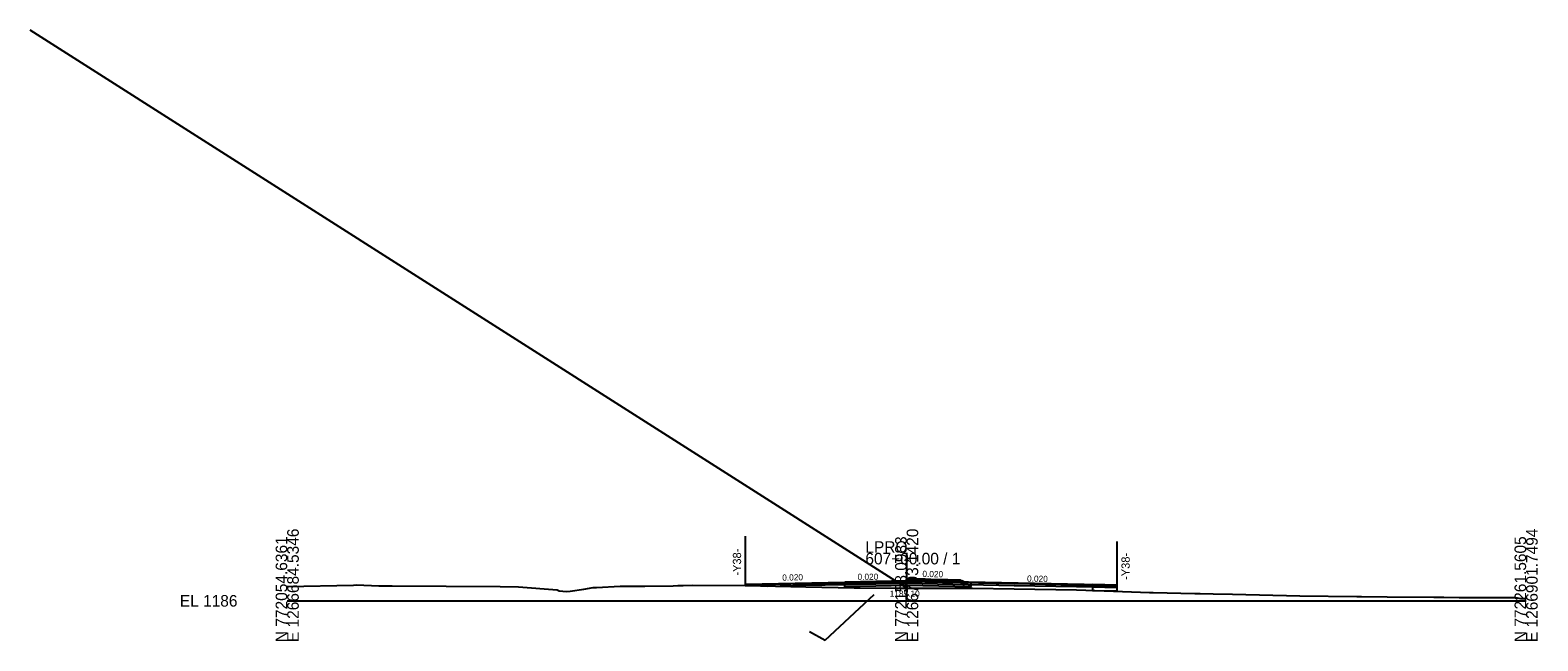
# Model space of a CAD drawing. Extents: x -3833 to 1267678, y -522 to 773248.
# Drawn here: x 937.8 to 1302.8, y 7990.3 to 8138.2 of the extents above; entities that cross this region are included whole.
import ezdxf

# ---------------------------------------------------------------- set-up
doc = ezdxf.new("R2010")
doc.units = 0
for name, color, linetype in [('Exist Cross Section Cell', 7, 'Continuous'), ('Exist XS Center Line Elevation Label', 7, 'Continuous'), ('Exist XS Ground Line', 7, 'Continuous'), ('Prop CMT DNC', 7, 'Continuous'), ('Prop CMT Pvmt Course 1', 7, 'Continuous'), ('Prop CMT Pvmt Course 2', 7, 'Continuous'), ('Prop CMT Pvmt Course 3', 7, 'Continuous'), ('Prop CMT Pvmt Course 4', 7, 'Continuous'), ('Prop CMT Shld Paved Course 1', 7, 'Continuous'), ('Prop CMT Shld Paved Course 2', 7, 'Continuous'), ('Prop CMT Subgrade Earthwork', 7, 'Continuous'), ('Prop Conc Curb and Gutter', 7, 'Continuous'), ('Prop Conc Island Cover', 7, 'Continuous'), ('Prop Corridor Mesh Bottom', 7, 'Continuous'), ('Prop XS Finish Grade', 7, 'Continuous'), ('Prop XS SE Text', 7, 'Continuous'), ('Prop XS Shear Point Element', 7, 'Continuous'), ('Prop XS Shear Point Label', 7, 'Continuous'), ('Scratch_Level_1', 7, 'Continuous'), ('Scratch_Level_5', 7, 'Continuous')]:
    doc.layers.add(name, color=color, linetype=linetype)

msp = doc.modelspace()

# ---------------------------------------------------------------- linework, layer by layer
at = {"layer": 'Exist Cross Section Cell'}
for p, q in [((1150, 8000), (1150, 8011.62)), ((1000, 8000), (1150, 8000)), ((1150, 8000), (1300, 8000))]:
    msp.add_line(p, q, dxfattribs=at)
at = {"layer": 'Exist XS Ground Line'}
for p, q in [((1000, 8003.45), (1016.03, 8003.78)), ((1016.03, 8003.78), (1016.76, 8003.87)), ((1016.76, 8003.87), (1022.17, 8003.64)), ((1022.17, 8003.64), (1025.41, 8003.65)), ((1025.41, 8003.65), (1051.56, 8003.47)), ((1051.56, 8003.47), (1056.01, 8003.4)), ((1056.01, 8003.4), (1065.39, 8002.68)), ((1068.55, 8002.3), (1071.81, 8002.83)), ((1071.81, 8002.83), (1074.05, 8003.22)), ((1074.05, 8003.22), (1074.91, 8003.25)), ((1074.91, 8003.25), (1080.65, 8003.54)), ((1080.65, 8003.54), (1082.76, 8003.54)), ((1082.76, 8003.54), (1086.56, 8003.58)), ((1086.56, 8003.58), (1093.44, 8003.65)), ((1093.44, 8003.65), (1094.58, 8003.67)), ((1094.58, 8003.67), (1095.84, 8003.71)), ((1095.84, 8003.71), (1098.22, 8003.77)), ((1098.22, 8003.77), (1110.86, 8003.7)), ((1110.86, 8003.7), (1125.56, 8003.38)), ((1125.56, 8003.38), (1137.29, 8003.12)), ((1137.29, 8003.12), (1147.49, 8003.1)), ((1147.49, 8003.1), (1150, 8003.1)), ((1150, 8003.1), (1165.98, 8003.05)), ((1165.98, 8003.05), (1176.07, 8002.89)), ((1176.07, 8002.89), (1191.16, 8002.63)), ((1065.39, 8002.68), (1065.88, 8002.44)), ((1065.88, 8002.44), (1067.66, 8002.27)), ((1067.66, 8002.27), (1068.55, 8002.3)), ((1191.16, 8002.63), (1200.06, 8002.33)), ((1200.06, 8002.33), (1208.78, 8002)), ((1208.78, 8002), (1209.71, 8001.98)), ((1209.71, 8001.98), (1219.77, 8001.75)), ((1219.77, 8001.75), (1221.09, 8001.73)), ((1221.09, 8001.73), (1224.2, 8001.68)), ((1224.2, 8001.68), (1228.87, 8001.6)), ((1228.87, 8001.6), (1245.23, 8001.23)), ((1245.23, 8001.23), (1259.04, 8001.04)), ((1259.04, 8001.04), (1260.15, 8001.02)), ((1260.15, 8001.02), (1266.32, 8000.94)), ((1266.32, 8000.94), (1277.65, 8000.89)), ((1277.65, 8000.89), (1280.1, 8000.87)), ((1280.1, 8000.87), (1283.82, 8000.84)), ((1283.82, 8000.84), (1284.64, 8000.83)), ((1284.64, 8000.83), (1295.8, 8000.76)), ((1295.8, 8000.76), (1297.44, 8000.81)), ((1297.44, 8000.81), (1298.66, 8000.58)), ((1298.66, 8000.58), (1300, 8000.55))]:
    msp.add_line(p, q, dxfattribs=at)
at = {"layer": 'Prop CMT Pvmt Course 1'}
for p, q in [((1111, 8004.06), (1135, 8004.54)), ((1111, 8004.06), (1111, 8004.06)), ((1135, 8004.54), (1135, 8004.54)), ((1135, 8004.54), (1135, 8004.54)), ((1135, 8004.54), (1135, 8004.29)), ((1135, 8004.29), (1135, 8004.29)), ((1148.88, 8004.82), (1148.89, 8004.82)), ((1148.89, 8004.57), (1148.88, 8004.57)), ((1148.88, 8004.57), (1148.88, 8004.57)), ((1164.53, 8004.55), (1164.56, 8004.55)), ((1164.56, 8004.55), (1164.57, 8004.55)), ((1164.57, 8004.31), (1164.57, 8004.3)), ((1201, 8003.82), (1165, 8004.54)), ((1165, 8004.54), (1165, 8004.54)), ((1165, 8004.54), (1165, 8004.54)), ((1165, 8004.29), (1165, 8004.29)), ((1195, 8003.94), (1195, 8003.69)), ((1201, 8003.82), (1195, 8003.94)), ((1195, 8003.69), (1195, 8003.94)), ((1195, 8003.94), (1195, 8003.94)), ((1195, 8003.94), (1195, 8003.94)), ((1195, 8003.94), (1201, 8003.82)), ((1195, 8003.69), (1201, 8003.57))]:
    msp.add_line(p, q, dxfattribs=at)
at = {"layer": 'Prop CMT Pvmt Course 2'}
for p, q in [((1150, 8004.59), (1135, 8004.29)), ((1135, 8004.29), (1135, 8004.29)), ((1135, 8004.29), (1135, 8003.96)), ((1135, 8003.96), (1150, 8004.26)), ((1135, 8003.96), (1135, 8003.96)), ((1148.88, 8004.57), (1148.89, 8004.57)), ((1148.88, 8004.32), (1148.88, 8004.32)), ((1150, 8004.59), (1150, 8004.59)), ((1150, 8004.59), (1150, 8004.59)), ((1150, 8004.26), (1150, 8004.26)), ((1150, 8004.26), (1150, 8004.26)), ((1163.81, 8003.52), (1163.81, 8004.44)), ((1165, 8004.29), (1165, 8004.29)), ((1165, 8003.96), (1165, 8003.96)), ((1195, 8003.69), (1195, 8003.36)), ((1201, 8003.57), (1195, 8003.69)), ((1195, 8003.36), (1201, 8003.24))]:
    msp.add_line(p, q, dxfattribs=at)
at = {"layer": 'Prop CMT Pvmt Course 3'}
msp.add_line((1148.88, 8003.94), (1148.88, 8003.95), dxfattribs=at)
at = {"layer": 'Prop CMT Pvmt Course 4'}
for p, q in [((1135, 8003.5), (1135, 8003.96)), ((1135, 8003.96), (1135, 8003.96)), ((1135, 8003.96), (1135, 8003.96)), ((1148.88, 8003.78), (1148.88, 8004.82)), ((1149.75, 8004.7), (1149.75, 8003.8)), ((1150, 8004.26), (1150, 8004.26)), ((1150, 8004.26), (1150, 8004.26)), ((1165, 8003.96), (1165, 8003.96)), ((1165, 8003.96), (1165, 8003.96)), ((1165.5, 8004.53), (1165.5, 8003.49)), ((1195, 8003.36), (1195, 8002.53)), ((1201, 8003.24), (1195, 8003.36)), ((1195, 8002.53), (1201, 8002.41))]:
    msp.add_line(p, q, dxfattribs=at)
at = {"layer": 'Prop CMT Shld Paved Course 1'}
for p, q in [((1150, 8004.84), (1135, 8004.54)), ((1135, 8004.54), (1135, 8004.54)), ((1135, 8004.54), (1135, 8004.29)), ((1165, 8004.54), (1150, 8004.84)), ((1150, 8004.84), (1150, 8004.84)), ((1150, 8004.59), (1150, 8004.59)), ((1150, 8004.59), (1150, 8004.59)), ((1150.1, 8005), (1150.1, 8005)), ((1165, 8004.54), (1165, 8004.54))]:
    msp.add_line(p, q, dxfattribs=at)
at = {"layer": 'Prop CMT Shld Paved Course 2'}
for p, q in [((1125.56, 8004.1), (1111, 8003.81)), ((1111, 8003.81), (1111, 8003.81)), ((1111, 8003.81), (1111, 8003.81)), ((1116.21, 8003.58), (1125.56, 8003.77)), ((1116.21, 8003.58), (1116.21, 8003.58)), ((1116.21, 8003.58), (1116.21, 8003.58)), ((1135, 8004.29), (1125.56, 8004.1)), ((1125.56, 8004.1), (1125.56, 8004.1)), ((1125.56, 8003.77), (1135, 8003.96)), ((1125.56, 8003.77), (1125.56, 8003.77)), ((1135, 8004.29), (1135, 8004.29)), ((1135, 8003.96), (1135, 8004.29)), ((1135, 8004.29), (1135, 8004.29)), ((1135, 8004.29), (1135, 8004.29)), ((1135, 8003.96), (1135, 8003.96)), ((1135, 8003.96), (1135, 8003.96)), ((1176.07, 8004.07), (1150, 8004.59)), ((1150, 8004.26), (1176.07, 8003.74)), ((1165, 8004.29), (1165, 8004.29)), ((1165.98, 8003.94), (1165.98, 8003.94)), ((1191.16, 8003.77), (1176.07, 8004.07)), ((1176.07, 8004.07), (1176.07, 8004.07)), ((1176.07, 8003.74), (1176.07, 8003.74)), ((1176.07, 8003.74), (1191.16, 8003.44)), ((1195, 8003.69), (1191.16, 8003.77)), ((1191.16, 8003.77), (1191.16, 8003.77)), ((1191.16, 8003.77), (1191.16, 8003.77)), ((1191.16, 8003.77), (1191.16, 8003.77)), ((1191.16, 8003.44), (1191.16, 8003.44)), ((1191.16, 8003.44), (1191.16, 8003.44)), ((1191.16, 8003.44), (1191.16, 8003.44)), ((1191.16, 8003.44), (1195, 8003.36)), ((1195, 8003.69), (1195, 8003.69)), ((1195, 8003.36), (1195, 8003.69)), ((1195, 8003.69), (1195, 8003.69)), ((1195, 8003.69), (1195, 8003.69)), ((1195, 8003.36), (1195, 8003.36)), ((1195, 8003.36), (1195, 8003.36))]:
    msp.add_line(p, q, dxfattribs=at)
at = {"layer": 'Prop CMT Subgrade Earthwork'}
for p, q in [((1135, 8003.5), (1150.01, 8003.8)), ((1135, 8003.17), (1135, 8003.5)), ((1150.01, 8003.8), (1165.5, 8003.49)), ((1165.5, 8003.05), (1165.5, 8003.49))]:
    msp.add_line(p, q, dxfattribs=at)
at = {"layer": 'Prop Conc Curb and Gutter'}
for p, q in [((1149.76, 8004.9), (1149.75, 8004.83)), ((1149.75, 8004.83), (1149.75, 8004.76)), ((1149.75, 8004.76), (1149.75, 8004.7)), ((1149.75, 8004.7), (1150.81, 8004.69)), ((1150.5, 8005.2), (1149.76, 8004.99)), ((1149.76, 8004.99), (1149.76, 8004.9)), ((1150.64, 8005.24), (1150.5, 8005.2)), ((1150.81, 8005.24), (1150.64, 8005.24)), ((1151.79, 8005.25), (1150.81, 8005.24)), ((1150.81, 8004.69), (1151.79, 8004.69)), ((1151.79, 8004.69), (1163.63, 8004.45)), ((1162.28, 8005.01), (1162.03, 8005.01)), ((1163.04, 8004.99), (1162.28, 8005.01)), ((1163.15, 8004.95), (1163.04, 8004.99)), ((1163.8, 8004.74), (1163.15, 8004.95)), ((1163.63, 8004.45), (1163.81, 8004.44)), ((1163.8, 8004.72), (1163.8, 8004.74)), ((1163.81, 8004.57), (1163.8, 8004.72)), ((1163.81, 8004.56), (1163.81, 8004.57)), ((1163.81, 8004.44), (1163.81, 8004.56))]:
    msp.add_line(p, q, dxfattribs=at)
at = {"layer": 'Prop Conc Island Cover'}
for p, q in [((1154.17, 8005.21), (1151.79, 8005.25)), ((1154.49, 8005.2), (1154.17, 8005.21)), ((1155.86, 8005.17), (1154.49, 8005.2)), ((1158.28, 8005.11), (1155.86, 8005.17)), ((1159.99, 8005.07), (1158.28, 8005.11)), ((1162.03, 8005.01), (1159.99, 8005.07))]:
    msp.add_line(p, q, dxfattribs=at)
at = {"layer": 'Prop Corridor Mesh Bottom'}
msp.add_line((1135, 8004.54), (1135, 8004.29), dxfattribs=at)
at = {"layer": 'Prop XS Finish Grade'}
for p, q in [((1151.79, 8005.25), (1154.17, 8005.21)), ((1154.17, 8005.21), (1154.49, 8005.2)), ((1154.49, 8005.2), (1155.86, 8005.17)), ((1155.86, 8005.17), (1158.28, 8005.11)), ((1158.28, 8005.11), (1159.99, 8005.07)), ((1159.99, 8005.07), (1162.03, 8005.01))]:
    msp.add_line(p, q, dxfattribs=at)
at = {"layer": 'Prop XS Shear Point Element'}
for p, q in [((1111, 8003.7), (1111, 8015.67)), ((1201, 8002.29), (1201, 8014.38))]:
    msp.add_line(p, q, dxfattribs=at)
at = {"layer": 'Scratch_Level_1'}
msp.add_line((1150, 8003.1), (937.75, 8138.16), dxfattribs=at)
at = {"layer": 'Scratch_Level_5'}
for p, q in [((1130.26, 7990.47), (1142.11, 8001.49)), ((1126.47, 7992.57), (1130.26, 7990.47))]:
    msp.add_line(p, q, dxfattribs=at)

# ---------------------------------------------------------------- texts
at = {"layer": 'Exist Cross Section Cell'}
for s, p in [('E 1266901.7494', (1302.8, 7990)), ('N 772054.6361', (1000, 7990)), ('E 1266684.5346', (1002.8, 7990)), ('N 772158.0983', (1150, 7990)), ('E 1266793.1420', (1152.8, 7990)), ('N 772261.5605', (1300, 7990))]:
    msp.add_text(s, height=2.8, rotation=90, dxfattribs=at).set_placement(p)
for s, p in [('LPRO', (1140, 8011.62)), ('607+00.00 / 1', (1140, 8008.82)), ('EL 1186', (974, 7998.6))]:
    msp.add_text(s, height=2.8, dxfattribs=at).set_placement(p)
at = {"layer": 'Exist XS Center Line Elevation Label'}
msp.add_text('1189.10', height=1.5, dxfattribs=at).set_placement((1145.9, 8000.98))
at = {"layer": 'Prop CMT DNC'}
for p in [(1111, 8004.06), (1135, 8004.54), (1135, 8004.54), (1150, 8004.84), (1165, 8004.54), (1165, 8004.54), (1201, 8003.82), (1201, 8003.82)]:
    msp.add_text('X', height=0.00025, dxfattribs=at).set_placement(p)
at = {"layer": 'Prop XS SE Text'}
for rotation, p in [(1.397, (1119.89, 8004.86)), (0.2693, (1138.11, 8005.06)), (358.8542, (1153.8, 8005.78)), (358.8542, (1179.14, 8004.64))]:
    msp.add_text('0.020', height=1.5, rotation=rotation, dxfattribs=at).set_placement(p)
at = {"layer": 'Prop XS Shear Point Label'}
for p in [(1109.91, 8006.09), (1204.01, 8005.06)]:
    msp.add_text('-Y38-', height=2, rotation=90, dxfattribs=at).set_placement(p)

doc.saveas('drawing.dxf')
